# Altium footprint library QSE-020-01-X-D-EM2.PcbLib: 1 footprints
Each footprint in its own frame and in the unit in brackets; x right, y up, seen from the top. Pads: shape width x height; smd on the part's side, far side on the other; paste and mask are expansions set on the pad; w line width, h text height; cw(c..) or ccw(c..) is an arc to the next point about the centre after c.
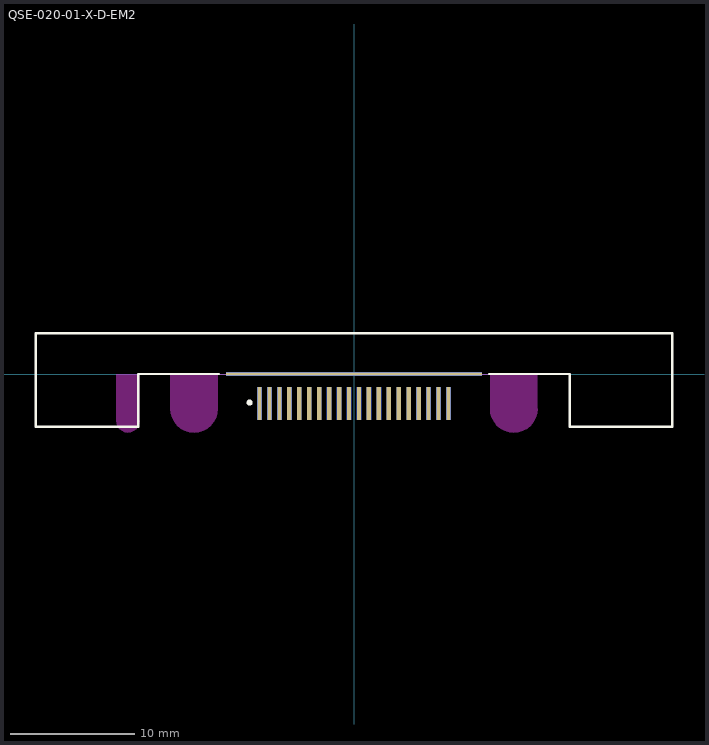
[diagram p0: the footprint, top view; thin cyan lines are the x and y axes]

## QSE-020-01-X-D-EM2 [mm] "0.80mm pitch, 40 pin, high speed socket; w/edge mounts"
height 3.63
pads (42):
  rect 0.35x2.65 smd mask+0: 1(-7.6,-2.375) 3(-6.8,-2.375) 5(-6,-2.375) 7(-5.2,-2.375) 9(-4.4,-2.375) 11(-3.6,-2.375) 13(-2.8,-2.375) 15(-2,-2.375) 17(-1.2,-2.375) 19(-0.4,-2.375) 21(0.4,-2.375) 23(1.2,-2.375) 25(2,-2.375) 27(2.8,-2.375) 29(3.6,-2.375) 31(4.4,-2.375) 33(5.2,-2.375) 35(6,-2.375) 37(6.8,-2.375) 39(7.6,-2.375)
  rect 0.35x2.65 smd far side mask+0: 2(-7.6,-2.375) 4(-6.8,-2.375) 6(-6,-2.375) 8(-5.2,-2.375) 10(-4.4,-2.375) 12(-3.6,-2.375) 14(-2.8,-2.375) 16(-2,-2.375) 18(-1.2,-2.375) 20(-0.4,-2.375) 22(0.4,-2.375) 24(1.2,-2.375) 26(2,-2.375) 28(2.8,-2.375) 30(3.6,-2.375) 32(4.4,-2.375) 34(5.2,-2.375) 36(6,-2.375) 38(6.8,-2.375) 40(7.6,-2.375)
  rect 20.58x0.25 smd mask+0: 41(0,0)
  rect 20.58x0.25 smd far side mask+0: 42(0,0)
Top Overlay:
  circle w0.25: c-8.4,-2.3 r0.125
  lines w0.2: -10.9,0 -17.35,0 -17.35,-4.226 -25.6,-4.226 -25.6,3.274 25.6,3.274 25.6,-4.226 17.35,-4.226 17.35,0 10.9,0
Top Paste:
  region: -10.29,0 10.29,0 10.29,-0.25 -10.29,-0.25
Bottom Paste:
  region: -10.29,0 10.29,0 10.29,-0.25 -10.29,-0.25
Top Solder:
  region: -10.29,0 10.29,0 10.29,-0.25 -10.29,-0.25
  region: 7.535,-2.55 7.665,-2.55 7.665,-3.7 7.535,-3.7
  region: 6.735,-2.55 6.865,-2.55 6.865,-3.7 6.735,-3.7
  region: 5.935,-2.55 6.065,-2.55 6.065,-3.7 5.935,-3.7
  region: 5.135,-2.55 5.265,-2.55 5.265,-3.7 5.135,-3.7
  region: 4.335,-2.55 4.465,-2.55 4.465,-3.7 4.335,-3.7
  region: 3.535,-2.55 3.665,-2.55 3.665,-3.7 3.535,-3.7
  region: 2.735,-2.55 2.865,-2.55 2.865,-3.7 2.735,-3.7
  region: 1.935,-2.55 2.065,-2.55 2.065,-3.7 1.935,-3.7
  region: 1.135,-2.55 1.265,-2.55 1.265,-3.7 1.135,-3.7
  region: 0.335,-2.55 0.465,-2.55 0.465,-3.7 0.335,-3.7
  region: -0.465,-2.55 -0.335,-2.55 -0.335,-3.7 -0.465,-3.7
  region: -1.265,-2.55 -1.135,-2.55 -1.135,-3.7 -1.265,-3.7
  region: -2.065,-2.55 -1.935,-2.55 -1.935,-3.7 -2.065,-3.7
  region: -2.865,-2.55 -2.735,-2.55 -2.735,-3.7 -2.865,-3.7
  region: -3.665,-2.55 -3.535,-2.55 -3.535,-3.7 -3.665,-3.7
  region: -4.465,-2.55 -4.335,-2.55 -4.335,-3.7 -4.465,-3.7
  region: -5.265,-2.55 -5.135,-2.55 -5.135,-3.7 -5.265,-3.7
  region: -6.065,-2.55 -5.935,-2.55 -5.935,-3.7 -6.065,-3.7
  region: -6.865,-2.55 -6.735,-2.55 -6.735,-3.7 -6.865,-3.7
  region: -7.665,-2.55 -7.535,-2.55 -7.535,-3.7 -7.665,-3.7
Bottom Solder:
  region: -10.29,0 10.29,0 10.29,-0.25 -10.29,-0.25
  region: 7.535,-2.55 7.665,-2.55 7.665,-3.7 7.535,-3.7
  region: 6.735,-2.55 6.865,-2.55 6.865,-3.7 6.735,-3.7
  region: 5.935,-2.55 6.065,-2.55 6.065,-3.7 5.935,-3.7
  region: 5.135,-2.55 5.265,-2.55 5.265,-3.7 5.135,-3.7
  region: 4.335,-2.55 4.465,-2.55 4.465,-3.7 4.335,-3.7
  region: 3.535,-2.55 3.665,-2.55 3.665,-3.7 3.535,-3.7
  region: 2.735,-2.55 2.865,-2.55 2.865,-3.7 2.735,-3.7
  region: 1.935,-2.55 2.065,-2.55 2.065,-3.7 1.935,-3.7
  region: 1.135,-2.55 1.265,-2.55 1.265,-3.7 1.135,-3.7
  region: 0.335,-2.55 0.465,-2.55 0.465,-3.7 0.335,-3.7
  region: -0.465,-2.55 -0.335,-2.55 -0.335,-3.7 -0.465,-3.7
  region: -1.265,-2.55 -1.135,-2.55 -1.135,-3.7 -1.265,-3.7
  region: -2.065,-2.55 -1.935,-2.55 -1.935,-3.7 -2.065,-3.7
  region: -2.865,-2.55 -2.735,-2.55 -2.735,-3.7 -2.865,-3.7
  region: -3.665,-2.55 -3.535,-2.55 -3.535,-3.7 -3.665,-3.7
  region: -4.465,-2.55 -4.335,-2.55 -4.335,-3.7 -4.465,-3.7
  region: -5.265,-2.55 -5.135,-2.55 -5.135,-3.7 -5.265,-3.7
  region: -6.065,-2.55 -5.935,-2.55 -5.935,-3.7 -6.065,-3.7
  region: -6.865,-2.55 -6.735,-2.55 -6.735,-3.7 -6.865,-3.7
  region: -7.665,-2.55 -7.535,-2.55 -7.535,-3.7 -7.665,-3.7
Keep-Out Layer:
  pour cut-out: -14.77,0 -14.779,-2.794 -14.742,-3.167 -14.634,-3.527 -14.457,-3.857 -14.219,-4.148 -13.928,-4.386 -13.598,-4.563 -13.238,-4.671 -12.865,-4.708 -12.492,-4.671 -12.132,-4.563 -11.802,-4.386 -11.511,-4.148 -11.273,-3.857 -11.096,-3.527 -10.988,-3.167 -10.951,-2.794 -10.96,-2.794 -10.96,0
  pour cut-out: 10.953,0 10.944,-2.794 10.981,-3.167 11.089,-3.527 11.266,-3.857 11.504,-4.148 11.795,-4.386 12.125,-4.563 12.485,-4.671 12.858,-4.708 13.231,-4.671 13.591,-4.563 13.921,-4.386 14.212,-4.148 14.45,-3.857 14.627,-3.527 14.735,-3.167 14.772,-2.794 14.763,-2.794 14.763,0
  pour cut-out: -19.119,0 -19.127,-3.775 -19.095,-4.017 -19.002,-4.242 -18.853,-4.436 -18.66,-4.585 -18.434,-4.678 -18.192,-4.71 -17.95,-4.678 -17.725,-4.585 -17.531,-4.436 -17.382,-4.242 -17.289,-4.017 -17.257,-3.775 -17.265,-3.775 -17.265,0
Mechanical 13:
  lines w0.1: -25.6,-4.226 -25.6,3.274 25.6,3.274 25.6,-4.226 17.35,-4.226 17.35,0 -17.35,0 -17.35,-4.226 -25.6,-4.226
  text ".Designator" at 0,0 h1.52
